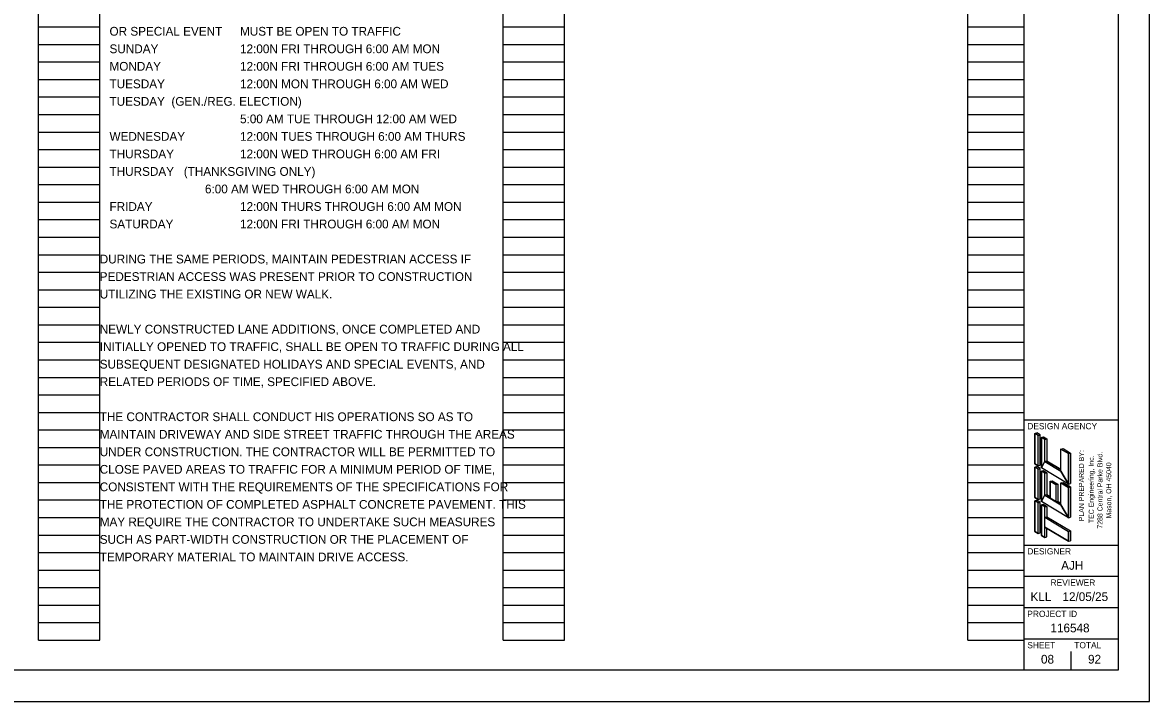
# Model space of a CAD drawing. Extents: x -8.1 to 34, y 0 to 22.
# Drawn here: x 16.01 to 34, y 0 to 10.85 of the extents above; entities that cross this region are included whole.
import ezdxf

# ---------------------------------------------------------------- set-up
doc = ezdxf.new("R2010")
doc.units = 0
for name, color, linetype in [('Default', 7, 'Continuous'), ('SH_Border', 7, 'Continuous'), ('SH_Cut_Line', 7, 'Continuous'), ('SH_Data', 7, 'Continuous'), ('SH_Text', 7, 'Continuous')]:
    doc.layers.add(name, color=color, linetype=linetype)

msp = doc.modelspace()

# ---------------------------------------------------------------- linework, layer by layer
at = {"layer": 'SH_Border'}
for p, q in [((32, 0.5), (32, 21.5)), ((32, 4.5), (33.5, 4.5)), ((32, 2.5), (33.5, 2.5)), ((32, 2), (33.5, 2)), ((32, 1.5), (33.5, 1.5)), ((32, 1), (33.5, 1))]:
    msp.add_line(p, q, dxfattribs=at)
msp.add_lwpolyline([(1.5, 21.5), (33.5, 21.5), (33.5, 0.5), (1.5, 0.5)], close=True, dxfattribs=at)
at = {"layer": 'SH_Cut_Line'}
msp.add_lwpolyline([(0, 0), (34, 0), (34, 22), (0, 22)], close=True, dxfattribs=at)
at = {"layer": 'SH_Data'}
for p, q in [((16.26, 0.98), (16.26, 21.14)), ((17.24, 0.98), (17.24, 21.14)), ((23.68, 0.98), (23.68, 21.14)), ((24.66, 0.98), (24.66, 21.14)), ((31.1, 0.98), (31.1, 21.14)), ((32, 0.98), (32, 21.14)), ((16.26, 10.78), (17.24, 10.78)), ((23.68, 10.78), (24.66, 10.78)), ((31.1, 10.78), (32, 10.78)), ((16.26, 10.5), (17.24, 10.5)), ((23.68, 10.5), (24.66, 10.5)), ((31.1, 10.5), (32, 10.5)), ((16.26, 10.22), (17.24, 10.22)), ((23.68, 10.22), (24.66, 10.22)), ((31.1, 10.22), (32, 10.22)), ((16.26, 9.94), (17.24, 9.94)), ((23.68, 9.94), (24.66, 9.94)), ((31.1, 9.94), (32, 9.94)), ((16.26, 9.66), (17.24, 9.66)), ((23.68, 9.66), (24.66, 9.66)), ((31.1, 9.66), (32, 9.66)), ((16.26, 9.38), (17.24, 9.38)), ((23.68, 9.38), (24.66, 9.38)), ((31.1, 9.38), (32, 9.38)), ((16.26, 9.1), (17.24, 9.1)), ((23.68, 9.1), (24.66, 9.1)), ((31.1, 9.1), (32, 9.1)), ((16.26, 8.82), (17.24, 8.82)), ((23.68, 8.82), (24.66, 8.82)), ((31.1, 8.82), (32, 8.82)), ((16.26, 8.54), (17.24, 8.54)), ((23.68, 8.54), (24.66, 8.54)), ((31.1, 8.54), (32, 8.54)), ((16.26, 8.26), (17.24, 8.26)), ((23.68, 8.26), (24.66, 8.26)), ((31.1, 8.26), (32, 8.26)), ((16.26, 7.98), (17.24, 7.98)), ((23.68, 7.98), (24.66, 7.98)), ((31.1, 7.98), (32, 7.98)), ((16.26, 7.7), (17.24, 7.7)), ((23.68, 7.7), (24.66, 7.7)), ((31.1, 7.7), (32, 7.7)), ((16.26, 7.42), (17.24, 7.42)), ((23.68, 7.42), (24.66, 7.42)), ((31.1, 7.42), (32, 7.42)), ((16.26, 7.14), (17.24, 7.14)), ((23.68, 7.14), (24.66, 7.14)), ((31.1, 7.14), (32, 7.14)), ((16.26, 6.86), (17.24, 6.86)), ((23.68, 6.86), (24.66, 6.86)), ((31.1, 6.86), (32, 6.86)), ((16.26, 6.58), (17.24, 6.58)), ((23.68, 6.58), (24.66, 6.58)), ((31.1, 6.58), (32, 6.58)), ((16.26, 6.3), (17.24, 6.3)), ((23.68, 6.3), (24.66, 6.3)), ((31.1, 6.3), (32, 6.3)), ((16.26, 6.02), (17.24, 6.02)), ((23.68, 6.02), (24.66, 6.02)), ((31.1, 6.02), (32, 6.02)), ((16.26, 5.74), (17.24, 5.74)), ((23.68, 5.74), (24.66, 5.74)), ((31.1, 5.74), (32, 5.74)), ((16.26, 5.46), (17.24, 5.46)), ((23.68, 5.46), (24.66, 5.46)), ((31.1, 5.46), (32, 5.46)), ((16.26, 5.18), (17.24, 5.18)), ((23.68, 5.18), (24.66, 5.18)), ((31.1, 5.18), (32, 5.18)), ((16.26, 4.9), (17.24, 4.9)), ((23.68, 4.9), (24.66, 4.9)), ((31.1, 4.9), (32, 4.9)), ((16.26, 4.62), (17.24, 4.62)), ((23.68, 4.62), (24.66, 4.62)), ((31.1, 4.62), (32, 4.62)), ((16.26, 4.34), (17.24, 4.34)), ((23.68, 4.34), (24.66, 4.34)), ((31.1, 4.34), (32, 4.34)), ((16.26, 4.06), (17.24, 4.06)), ((23.68, 4.06), (24.66, 4.06)), ((31.1, 4.06), (32, 4.06)), ((16.26, 3.78), (17.24, 3.78)), ((23.68, 3.78), (24.66, 3.78)), ((31.1, 3.78), (32, 3.78)), ((16.26, 3.5), (17.24, 3.5)), ((23.68, 3.5), (24.66, 3.5)), ((31.1, 3.5), (32, 3.5)), ((32.75, 3.5), (32.75, 3.5)), ((16.26, 3.22), (17.24, 3.22)), ((23.68, 3.22), (24.66, 3.22)), ((31.1, 3.22), (32, 3.22)), ((16.26, 2.94), (17.24, 2.94)), ((23.68, 2.94), (24.66, 2.94)), ((31.1, 2.94), (32, 2.94)), ((16.26, 2.66), (17.24, 2.66)), ((23.68, 2.66), (24.66, 2.66)), ((31.1, 2.66), (32, 2.66)), ((16.26, 2.38), (17.24, 2.38)), ((23.68, 2.38), (24.66, 2.38)), ((31.1, 2.38), (32, 2.38)), ((16.26, 2.1), (17.24, 2.1)), ((23.68, 2.1), (24.66, 2.1)), ((31.1, 2.1), (32, 2.1)), ((16.26, 1.82), (17.24, 1.82)), ((23.68, 1.82), (24.66, 1.82)), ((31.1, 1.82), (32, 1.82)), ((16.26, 1.54), (17.24, 1.54)), ((23.68, 1.54), (24.66, 1.54)), ((31.1, 1.54), (32, 1.54)), ((16.26, 1.26), (17.24, 1.26)), ((23.68, 1.26), (24.66, 1.26)), ((31.1, 1.26), (32, 1.26)), ((16.26, 0.98), (17.24, 0.98)), ((23.68, 0.98), (24.66, 0.98)), ((31.1, 0.98), (32, 0.98)), ((32.75, 0.5), (32.75, 0.8)), ((32.375, 0.675), (32.375, 0.675))]:
    msp.add_line(p, q, dxfattribs=at)
at = {"layer": 'SH_Text'}
for p, q in [((32.169, 4.285), (32.201, 4.294)), ((32.169, 3.799), (32.169, 4.285)), ((32.223, 4.253), (32.169, 4.285)), ((32.255, 4.261), (32.201, 4.294)), ((32.223, 4.253), (32.255, 4.261)), ((32.223, 3.767), (32.223, 4.253)), ((32.255, 3.775), (32.255, 4.261)), ((32.277, 4.221), (32.309, 4.229)), ((32.331, 4.188), (32.277, 4.221)), ((32.277, 3.735), (32.277, 4.221)), ((32.309, 4.229), (32.363, 4.196)), ((32.331, 4.188), (32.363, 4.196)), ((32.331, 3.837), (32.331, 4.188)), ((32.363, 4.196), (32.363, 3.845)), ((32.587, 4.034), (32.62, 4.042)), ((32.587, 3.683), (32.587, 4.034)), ((32.709, 3.961), (32.587, 4.034)), ((32.62, 4.042), (32.741, 3.97)), ((32.709, 3.961), (32.741, 3.97)), ((32.709, 3.475), (32.709, 3.961)), ((32.741, 3.97), (32.741, 3.484)), ((32.223, 3.767), (32.169, 3.799)), ((32.331, 3.837), (32.363, 3.845)), ((32.587, 3.683), (32.331, 3.837)), ((32.363, 3.845), (32.587, 3.711)), ((32.169, 3.745), (32.201, 3.754)), ((32.169, 3.259), (32.169, 3.745)), ((32.223, 3.713), (32.169, 3.745)), ((32.255, 3.722), (32.201, 3.754)), ((32.223, 3.767), (32.255, 3.775)), ((32.223, 3.713), (32.255, 3.722)), ((32.223, 3.227), (32.223, 3.713)), ((32.255, 3.236), (32.255, 3.722)), ((32.709, 3.475), (32.277, 3.735)), ((32.277, 3.681), (32.309, 3.689)), ((32.277, 3.195), (32.277, 3.681)), ((32.331, 3.648), (32.277, 3.681)), ((32.309, 3.689), (32.363, 3.656)), ((32.331, 3.648), (32.363, 3.656)), ((32.331, 3.297), (32.331, 3.648)), ((32.363, 3.656), (32.363, 3.305)), ((32.415, 3.519), (32.448, 3.527)), ((32.415, 3.519), (32.415, 3.247)), ((32.415, 3.519), (32.503, 3.466)), ((32.448, 3.527), (32.535, 3.474)), ((32.503, 3.466), (32.535, 3.474)), ((32.503, 3.466), (32.503, 3.194)), ((32.535, 3.474), (32.535, 3.202)), ((32.587, 3.494), (32.62, 3.502)), ((32.587, 3.143), (32.587, 3.494)), ((32.709, 3.421), (32.587, 3.494)), ((32.62, 3.502), (32.741, 3.43)), ((32.709, 3.475), (32.741, 3.484)), ((32.709, 3.421), (32.741, 3.43)), ((32.709, 2.935), (32.709, 3.421)), ((32.741, 3.43), (32.741, 2.944)), ((32.223, 3.227), (32.169, 3.259)), ((32.331, 3.297), (32.363, 3.305)), ((32.415, 3.247), (32.331, 3.297)), ((32.363, 3.305), (32.415, 3.274)), ((32.169, 3.205), (32.201, 3.215)), ((32.169, 2.719), (32.169, 3.205)), ((32.223, 3.173), (32.169, 3.205)), ((32.255, 3.181), (32.201, 3.215)), ((32.222, 3.173), (32.255, 3.181)), ((32.223, 3.227), (32.255, 3.236)), ((32.223, 2.687), (32.223, 3.173)), ((32.255, 2.695), (32.255, 3.181)), ((32.709, 2.935), (32.277, 3.195)), ((32.277, 3.141), (32.309, 3.151)), ((32.331, 3.108), (32.277, 3.141)), ((32.277, 2.655), (32.277, 3.141)), ((32.309, 3.151), (32.363, 3.116)), ((32.331, 3.108), (32.363, 3.116)), ((32.331, 2.944), (32.331, 3.108)), ((32.363, 3.116), (32.363, 2.952)), ((32.503, 3.194), (32.535, 3.202)), ((32.587, 3.143), (32.503, 3.194)), ((32.535, 3.202), (32.587, 3.171)), ((32.331, 2.944), (32.363, 2.952)), ((32.331, 2.944), (32.709, 2.717)), ((32.363, 2.952), (32.741, 2.725)), ((32.709, 2.935), (32.741, 2.944)), ((32.223, 2.687), (32.169, 2.719)), ((32.331, 2.787), (32.709, 2.56)), ((32.331, 2.622), (32.331, 2.787)), ((32.363, 2.63), (32.363, 2.767)), ((32.709, 2.717), (32.741, 2.725)), ((32.709, 2.56), (32.709, 2.717)), ((32.741, 2.725), (32.741, 2.568)), ((32.223, 2.687), (32.255, 2.695)), ((32.331, 2.622), (32.277, 2.655)), ((32.331, 2.622), (32.363, 2.63)), ((32.709, 2.56), (32.741, 2.568))]:
    msp.add_line(p, q, dxfattribs=at)
for points in [[(32.169, 3.799), (32.223, 3.767), (32.223, 4.253), (32.169, 4.285)], [(32.277, 3.735), (32.331, 3.837), (32.331, 4.188), (32.277, 4.221)], [(32.709, 3.475), (32.587, 3.683), (32.587, 4.034), (32.709, 3.961)], [(32.277, 3.735), (32.331, 3.837), (32.587, 3.683), (32.709, 3.475)], [(32.169, 3.259), (32.223, 3.227), (32.223, 3.713), (32.169, 3.745)], [(32.277, 3.195), (32.331, 3.297), (32.331, 3.648), (32.277, 3.681)], [(32.415, 3.247), (32.415, 3.519), (32.503, 3.466), (32.503, 3.194)], [(32.709, 2.935), (32.587, 3.143), (32.587, 3.494), (32.709, 3.421)], [(32.277, 3.195), (32.331, 3.297), (32.587, 3.143), (32.709, 2.935)], [(32.169, 2.719), (32.223, 2.687), (32.223, 3.173), (32.169, 3.205)], [(32.277, 2.655), (32.331, 2.622), (32.331, 3.108), (32.277, 3.141)], [(32.331, 2.787), (32.331, 2.944), (32.709, 2.717), (32.709, 2.56)]]:
    msp.add_lwpolyline(points, close=True, dxfattribs=at)

# ---------------------------------------------------------------- texts
at = {"layer": 'Default'}
for s, p in [('PLAN PREPARED BY:', (32.954, 2.88)), ('TEC Engineering, Inc.', (33.11, 2.851)), ('7288 Central Parke Blvd.', (33.25, 2.762)), ('Mason, OH 45040', (33.39, 2.925))]:
    msp.add_text(s, height=0.08, rotation=90, dxfattribs=at).set_placement(p)
at = {"layer": 'SH_Data'}
for s, height, p in [('DESIGN AGENCY', 0.1, (32.05, 4.35)), ('DESIGNER', 0.1, (32.05, 2.35)), ('AJH', 0.14, (32.59, 2.105)), ('REVIEWER', 0.1, (32.422, 1.85)), ('KLL', 0.14, (32.101, 1.605)), ('12/05/25', 0.14, (32.611, 1.605)), ('PROJECT ID', 0.1, (32.05, 1.35)), ('116548', 0.14, (32.419, 1.105)), ('SHEET', 0.1, (32.05, 0.85)), ('TOTAL', 0.1, (32.8, 0.85)), ('08', 0.14, (32.268, 0.605)), ('92', 0.14, (33.019, 0.605))]:
    msp.add_text(s, height=height, dxfattribs=at).set_placement(p)
at = {"layer": 'SH_Text'}
for s, p in [('   OR SPECIAL EVENT   ', (17.24, 10.64)), ('MUST BE OPEN TO TRAFFIC', (19.48, 10.64)), ('   SUNDAY     ', (17.24, 10.36)), ('12:00N FRI THROUGH 6:00 AM MON', (19.48, 10.36)), ('   MONDAY     ', (17.24, 10.08)), ('12:00N FRI THROUGH 6:00 AM TUES', (19.48, 10.08)), ('   TUESDAY    ', (17.24, 9.8)), ('12:00N MON THROUGH 6:00 AM WED', (19.48, 9.8)), ('   TUESDAY  (GEN./REG. ELECTION)', (17.24, 9.52)), ('5:00 AM TUE THROUGH 12:00 AM WED', (19.48, 9.24)), ('   WEDNESDAY  ', (17.24, 8.96)), ('12:00N TUES THROUGH 6:00 AM THURS', (19.48, 8.96)), ('   THURSDAY   ', (17.24, 8.68)), ('12:00N WED THROUGH 6:00 AM FRI', (19.48, 8.68)), ('   THURSDAY   (THANKSGIVING ONLY)', (17.24, 8.4)), ('6:00 AM WED THROUGH 6:00 AM MON', (18.92, 8.12)), ('   FRIDAY     ', (17.24, 7.84)), ('12:00N THURS THROUGH 6:00 AM MON', (19.48, 7.84)), ('   SATURDAY   ', (17.24, 7.56)), ('12:00N FRI THROUGH 6:00 AM MON', (19.48, 7.56)), ('DURING THE SAME PERIODS, MAINTAIN PEDESTRIAN ACCESS IF ', (17.24, 7)), ('PEDESTRIAN ACCESS WAS PRESENT PRIOR TO CONSTRUCTION ', (17.24, 6.72)), ('UTILIZING THE EXISTING OR NEW WALK. ', (17.24, 6.44)), ('NEWLY CONSTRUCTED LANE ADDITIONS, ONCE COMPLETED AND ', (17.24, 5.88)), ('INITIALLY OPENED TO TRAFFIC, SHALL BE OPEN TO TRAFFIC DURING ALL ', (17.24, 5.6)), ('SUBSEQUENT DESIGNATED HOLIDAYS AND SPECIAL EVENTS, AND ', (17.24, 5.32)), ('RELATED PERIODS OF TIME, SPECIFIED ABOVE. ', (17.24, 5.04)), ('THE CONTRACTOR SHALL CONDUCT HIS OPERATIONS SO AS TO ', (17.24, 4.48)), ('MAINTAIN DRIVEWAY AND SIDE STREET TRAFFIC THROUGH THE AREAS ', (17.24, 4.2)), ('UNDER CONSTRUCTION. THE CONTRACTOR WILL BE PERMITTED TO ', (17.24, 3.92)), ('CLOSE PAVED AREAS TO TRAFFIC FOR A MINIMUM PERIOD OF TIME, ', (17.24, 3.64)), ('CONSISTENT WITH THE REQUIREMENTS OF THE SPECIFICATIONS FOR ', (17.24, 3.36)), ('THE PROTECTION OF COMPLETED ASPHALT CONCRETE PAVEMENT. THIS ', (17.24, 3.08)), ('MAY REQUIRE THE CONTRACTOR TO UNDERTAKE SUCH MEASURES ', (17.24, 2.8)), ('SUCH AS PART-WIDTH CONSTRUCTION OR THE PLACEMENT OF ', (17.24, 2.52)), ('TEMPORARY MATERIAL TO MAINTAIN DRIVE ACCESS. ', (17.24, 2.24))]:
    msp.add_text(s, height=0.14, dxfattribs=at).set_placement(p)

doc.saveas('drawing.dxf')
